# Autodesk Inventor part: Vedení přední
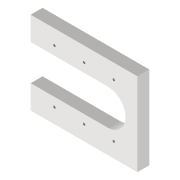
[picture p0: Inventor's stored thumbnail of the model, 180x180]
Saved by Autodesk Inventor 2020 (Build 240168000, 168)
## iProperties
Created: 2025-03
Part Number: Vedení přední
Material: Ocel
Document SubType Name: Modeling
Designer: doma
Density: 7.85 g/cm^3
Appearance: Plech
Mass: 2497.2 g
Surface Area: 520.549 cm^2
Volume: 318.115 cm^3
Author: doma
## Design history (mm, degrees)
sketch "Náčrt1"
  geometry: L1 (785.05, 270.193)-(965.05, 270.193); L2 (965.05, 270.193)-(965.05, 410.193); L3 (965.05, 410.193)-(785.05, 410.193); L4 (785.05, 410.193)-(785.05, 270.193); L5 (835.05, 370.193)-(915.05, 370.193); L6 (915.05, 310.193)-(835.05, 310.193); L7 (835.05, 370.193)-(785.05, 370.193); L8 (835.05, 310.193)-(785.05, 310.193); A1 r 30 centre (915.05, 340.193) between (915.05, 310.193) and (915.05, 370.193); A2 r 30 centre (835.05, 340.193) between (835.05, 370.193) and (835.05, 310.193); 9 further points
  constraints: 16 end point, 4 point on circle, 2 centre point, 2 perpendicular, 2 point on line
extrude "Vysunutí1" new body sketch "Náčrt1" distance "d54" = 20; taper "d55" = 0 deg
sketch "Náčrt2"
  geometry: L1 (965.05, 410.193)-(785.05, 410.193) reference; L2 (785.05, 410.193)-(785.05, 385.193); L3 (785.05, 410.193)-(785.05, 370.193) reference; L4 (785.05, 385.193)-(965.05, 385.193); L5 (965.05, 270.193)-(965.05, 410.193) reference; L6 (965.05, 340.193)-(868.872, 340.193); 7 further points
  constraints: 6 end point, 4 point on line, 3 symmetric about line, 2 midpoint, 1 horizontal, 1 perpendicular
  dimensions: "d56" = 25 distance of L1.end L2.end; "d57" = 50 distance of point (925.05, 385.193) point (875.05, 385.193); "d58" = 50 distance of point (825.05, 385.193) point (875.05, 385.193)
hole "Díra1" sketch "Náčrt2" at (875.05, 385.193), (825.05, 385.193), (925.05, 385.193), (825.05, 295.193), (875.05, 295.193), (925.05, 295.193) diameter "d59" = 4.134; stored, may be unused: countersink angle "d63" = 90 deg, drill point angle "d65" = 118 deg; dims "d60" = 10, "d61" = 4, "d62" = 2, "d64" = 14.2
node "Těleso1"
